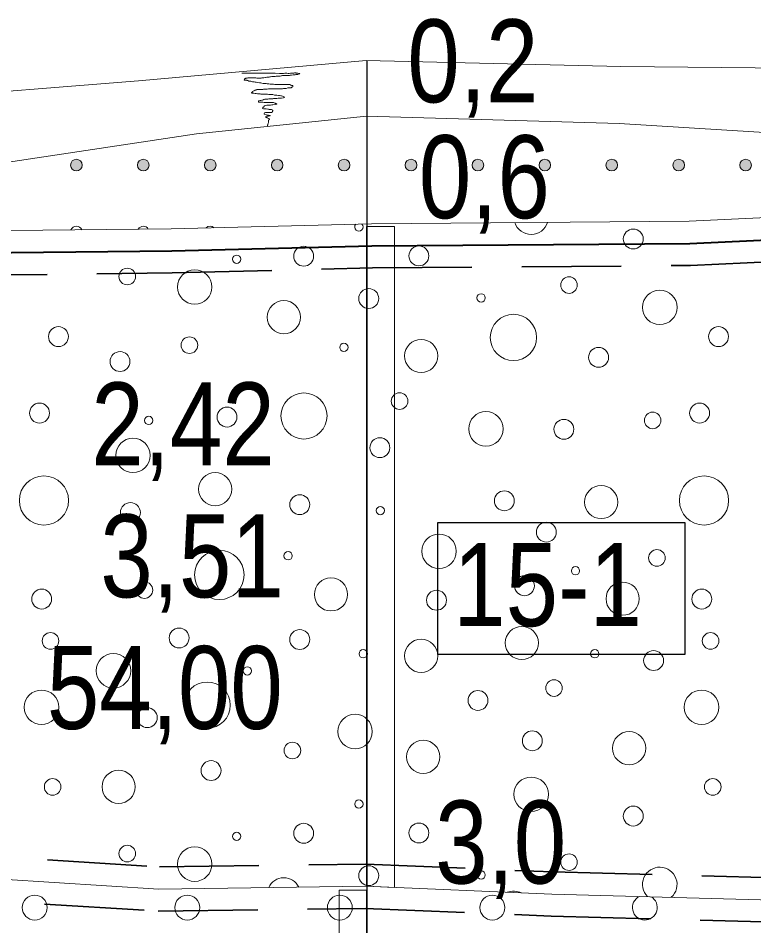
# Model space of a CAD drawing. Extents: x 640121 to 640955, y 6441885 to 6442246.
# Drawn here: x 640421.76 to 640448.36, y 6442180.31 to 6442213.13 of the extents above; entities that cross this region are included whole.
import ezdxf
from ezdxf.enums import TextEntityAlignment as Align

# ---------------------------------------------------------------- set-up
doc = ezdxf.new("R2010")
doc.units = 0
doc.header["$LTSCALE"] = 1.2
doc.linetypes.add('MEDIUM_DASHED', pattern=[4.5, 3, -1.5])
for name, color, linetype, lineweight in [('31', 7, 'Continuous', 13), ('32', 7, 'Continuous', 13), ('33', 7, 'Continuous', 13), ('35', 7, 'Continuous', 35), ('40', 7, 'Continuous', 13), ('41', 7, 'Continuous', 13), ('42', 7, 'Continuous', 13), ('45', 7, 'Continuous', 13)]:
    doc.layers.add(name, color=color, linetype=linetype, lineweight=lineweight)

msp = doc.modelspace()

# ---------------------------------------------------------------- hatches: boundary and pattern name
at = {"layer": '45'}
for points in [[(640424.077, 6442207.821, 1), (640423.657, 6442207.821, 1)], [(640426.497, 6442207.821, 1), (640426.077, 6442207.821, 1)], [(640428.917, 6442207.821, 1), (640428.497, 6442207.821, 1)], [(640431.337, 6442207.821, 1), (640430.917, 6442207.821, 1)], [(640433.757, 6442207.821, 1), (640433.337, 6442207.821, 1)], [(640436.177, 6442207.821, 1), (640435.757, 6442207.821, 1)], [(640438.597, 6442207.821, 1), (640438.177, 6442207.821, 1)], [(640441.017, 6442207.821, 1), (640440.597, 6442207.821, 1)], [(640443.437, 6442207.821, 1), (640443.017, 6442207.821, 1)], [(640445.857, 6442207.821, 1), (640445.437, 6442207.821, 1)], [(640448.277, 6442207.821, 1), (640447.857, 6442207.821, 1)]]:
    msp.add_hatch(color=256, dxfattribs=at).paths.add_polyline_path(points)

# ---------------------------------------------------------------- linework, layer by layer
at = {"layer": '31'}
for points in [[(640362.7, 6442207.53), (640371.1, 6442207.66), (640378.91, 6442207.96), (640387.66, 6442208.39), (640395.09, 6442208.91), (640403.04, 6442209.13), (640410.1, 6442209.62), (640417.94, 6442210.22), (640426.11, 6442210.87), (640434.35, 6442211.6), (640443.55, 6442211.39), (640450.84, 6442211.31), (640460.31, 6442211.42), (640471.64, 6442211.39), (640480.39, 6442211.46), (640490.9, 6442211.02), (640496.37, 6442211.02), (640502.28, 6442211.46), (640506.95, 6442212.04), (640510.5, 6442212.56)], [(640362.55, 6442203.68), (640369.1, 6442203.88), (640381.31, 6442204.1), (640393.24, 6442204.9), (640403.15, 6442205.61), (640412.11, 6442206.42), (640420.43, 6442207.78), (640428.21, 6442208.95), (640434.36, 6442209.59), (640443.5, 6442209.32), (640451.09, 6442208.86), (640456.15, 6442208.6), (640464.23, 6442208.39), (640474.43, 6442207.96), (640479.86, 6442207.51), (640485.77, 6442207.28), (640492.16, 6442206.96), (640495.99, 6442206.92), (640502.28, 6442207.34), (640510.5, 6442208.25)], [(640393.24, 6442204.9), (640408.33, 6442204.95), (640419.16, 6442205.43), (640427.3, 6442205.52), (640434.54, 6442205.7), (640446.03, 6442205.79), (640457.52, 6442206.33), (640468.28, 6442206.96), (640474.79, 6442207.15), (640481.17, 6442207.46)], [(640361.87, 6442180.35), (640370.38, 6442181.71), (640378.83, 6442182.99), (640382.86, 6442183.28), (640390.58, 6442183.39), (640398.35, 6442183.34), (640407.42, 6442182.84), (640417.38, 6442182.24), (640426.85, 6442181.64), (640434.32, 6442181.74), (640441.06, 6442181.46), (640449.93, 6442181.22), (640459.93, 6442181.24), (640467.81, 6442181.49), (640476.37, 6442181.44), (640484.64, 6442181.24), (640496.4, 6442181.04), (640502.87, 6442181.04), (640510.5, 6442181.13)]]:
    msp.add_lwpolyline(points, dxfattribs=at)
at = {"layer": '32', "lineweight": 25}
msp.add_line((640434.37, 6442211.6), (640434.37, 6442111.6), dxfattribs=at)
at = {"layer": '33'}
for points in [[(640435.37, 6442181.7), (640435.37, 6442205.6), (640434.36, 6442205.6), (640434.36, 6442181.74), (640434.36, 6442181.74)], [(640433.37, 6442181.6), (640433.37, 6442146.6), (640434.36, 6442146.6), (640434.36, 6442181.6)]]:
    msp.add_lwpolyline(points, close=True, dxfattribs=at)
at = {"layer": '33', "lineweight": 25}
msp.add_lwpolyline([(640436.94, 6442194.9), (640445.87, 6442194.9), (640445.87, 6442190.12), (640436.94, 6442190.12)], close=True, dxfattribs=at)
at = {"layer": '35', "lineweight": 40}
msp.add_lwpolyline([(640393.27, 6442204.1), (640408.35, 6442204.15), (640419.19, 6442204.63), (640427.32, 6442204.72), (640434.55, 6442204.9), (640446.05, 6442204.99), (640457.56, 6442205.53), (640468.31, 6442206.17), (640474.82, 6442206.35), (640481.18, 6442206.66)], dxfattribs=at)
at = {"layer": '35', "linetype": 'MEDIUM_DASHED'}
for points in [[(640393.27, 6442203.3), (640408.37, 6442203.35), (640419.21, 6442203.83), (640427.33, 6442203.92), (640434.57, 6442204.1), (640446.07, 6442204.19), (640457.6, 6442204.73), (640468.35, 6442205.37), (640474.85, 6442205.55), (640481.22, 6442205.86)], [(640379.57, 6442183.85), (640382.82, 6442184.08), (640390.58, 6442184.19), (640398.38, 6442184.14), (640407.47, 6442183.64), (640417.43, 6442183.04), (640426.87, 6442182.44), (640434.33, 6442182.54), (640441.09, 6442182.26), (640449.94, 6442182.02), (640459.92, 6442182.04), (640467.8, 6442182.29), (640476.38, 6442182.24), (640484.66, 6442182.04), (640494.87, 6442181.87)], [(640377.97, 6442182.13), (640382.89, 6442182.48), (640390.58, 6442182.59), (640398.33, 6442182.54), (640407.37, 6442182.04), (640417.33, 6442181.44), (640426.83, 6442180.84), (640434.31, 6442180.94), (640441.03, 6442180.66), (640449.92, 6442180.42), (640459.94, 6442180.44), (640467.82, 6442180.69), (640476.36, 6442180.64), (640484.62, 6442180.44), (640494.87, 6442180.27)]]:
    msp.add_lwpolyline(points, dxfattribs=at)
at = {"layer": '40'}
for points in [[(640429.85, 6442211.15), (640429.88, 6442211.15), (640429.93, 6442211.15), (640429.98, 6442211.15), (640430, 6442211.15), (640430.05, 6442211.15), (640430.13, 6442211.15), (640430.29, 6442211.15), (640430.38, 6442211.15), (640430.4, 6442211.15), (640430.42, 6442211.15), (640430.45, 6442211.15), (640430.49, 6442211.15), (640430.55, 6442211.15), (640430.59, 6442211.15), (640430.62, 6442211.15), (640430.66, 6442211.15), (640430.7, 6442211.15), (640430.73, 6442211.15), (640430.78, 6442211.15), (640430.8, 6442211.15), (640430.84, 6442211.15), (640430.88, 6442211.15), (640431.05, 6442211.14), (640431.21, 6442211.13), (640431.26, 6442211.13), (640431.29, 6442211.13), (640431.3, 6442211.13), (640431.33, 6442211.13), (640431.36, 6442211.13), (640431.41, 6442211.14), (640431.44, 6442211.14), (640431.45, 6442211.14), (640431.47, 6442211.14), (640431.48, 6442211.14), (640431.52, 6442211.13), (640431.54, 6442211.13), (640431.56, 6442211.13), (640431.61, 6442211.14), (640431.64, 6442211.14), (640431.68, 6442211.15), (640431.69, 6442211.15), (640431.73, 6442211.15), (640431.75, 6442211.16), (640431.77, 6442211.16), (640431.8, 6442211.16), (640431.81, 6442211.15), (640431.83, 6442211.15), (640431.86, 6442211.14), (640431.87, 6442211.14)], [(640430.61, 6442210.98), (640430.6, 6442210.98), (640430.57, 6442210.98), (640430.55, 6442210.97), (640430.53, 6442210.97), (640430.51, 6442210.97), (640430.49, 6442210.97), (640430.46, 6442210.97), (640430.44, 6442210.97), (640430.4, 6442210.97), (640430.39, 6442210.97), (640430.36, 6442210.98), (640430.34, 6442210.98), (640430.32, 6442210.98), (640430.3, 6442210.98), (640430.28, 6442210.98), (640430.25, 6442210.98), (640430.22, 6442210.98), (640430.2, 6442210.98), (640430.18, 6442210.98), (640430.15, 6442210.98), (640430.13, 6442210.98), (640430.11, 6442210.98), (640430.09, 6442210.98), (640430.07, 6442210.98), (640430.04, 6442210.97), (640430.03, 6442210.96), (640430, 6442210.96), (640429.98, 6442210.95), (640429.97, 6442210.95), (640429.96, 6442210.94), (640429.95, 6442210.93), (640429.94, 6442210.91), (640429.95, 6442210.89), (640430, 6442210.89), (640430.03, 6442210.89), (640430.04, 6442210.88), (640430.07, 6442210.88), (640430.09, 6442210.87), (640430.1, 6442210.86), (640430.13, 6442210.86), (640430.15, 6442210.86), (640430.17, 6442210.85), (640430.21, 6442210.84), (640430.24, 6442210.83), (640430.28, 6442210.83), (640430.3, 6442210.83), (640430.33, 6442210.82), (640430.37, 6442210.82), (640430.42, 6442210.81)], [(640431.87, 6442211.14), (640431.9, 6442211.13), (640431.92, 6442211.13), (640431.94, 6442211.13), (640431.95, 6442211.12), (640431.94, 6442211.12), (640431.95, 6442211.12), (640431.93, 6442211.12), (640431.9, 6442211.11), (640431.87, 6442211.1), (640431.86, 6442211.1), (640431.83, 6442211.1), (640431.81, 6442211.1), (640431.8, 6442211.1), (640431.78, 6442211.09), (640431.75, 6442211.09), (640431.72, 6442211.08), (640431.7, 6442211.08), (640431.64, 6442211.07), (640431.62, 6442211.07), (640431.6, 6442211.07), (640431.57, 6442211.06), (640431.55, 6442211.06), (640431.53, 6442211.06), (640431.5, 6442211.06), (640431.48, 6442211.06), (640431.43, 6442211.06), (640431.4, 6442211.06), (640431.36, 6442211.06), (640431.32, 6442211.06), (640431.29, 6442211.05), (640431.27, 6442211.05), (640431.24, 6442211.04), (640431.21, 6442211.04), (640431.12, 6442211.04), (640431.11, 6442211.04), (640431.09, 6442211.04), (640431.05, 6442211.03), (640431, 6442211.03), (640430.96, 6442211.02), (640430.93, 6442211.02), (640430.89, 6442211.01), (640430.86, 6442211.01), (640430.84, 6442211), (640430.81, 6442211), (640430.79, 6442211), (640430.78, 6442211), (640430.75, 6442211), (640430.72, 6442210.99), (640430.7, 6442210.99), (640430.64, 6442210.98), (640430.61, 6442210.98)], [(640430.42, 6442210.81), (640430.49, 6442210.8), (640430.54, 6442210.79), (640430.57, 6442210.78), (640430.62, 6442210.77), (640430.67, 6442210.77), (640430.7, 6442210.77), (640430.73, 6442210.77), (640430.76, 6442210.76), (640430.8, 6442210.76), (640430.83, 6442210.76), (640430.87, 6442210.75), (640430.91, 6442210.75), (640430.95, 6442210.75), (640431, 6442210.75), (640431.04, 6442210.74), (640431.07, 6442210.74), (640431.09, 6442210.74), (640431.12, 6442210.74), (640431.16, 6442210.74), (640431.2, 6442210.74), (640431.25, 6442210.74), (640431.29, 6442210.74), (640431.32, 6442210.74), (640431.36, 6442210.74), (640431.38, 6442210.74), (640431.41, 6442210.74), (640431.44, 6442210.74), (640431.47, 6442210.74), (640431.5, 6442210.74), (640431.53, 6442210.73), (640431.59, 6442210.73), (640431.62, 6442210.71), (640431.65, 6442210.7), (640431.68, 6442210.7), (640431.69, 6442210.69), (640431.69, 6442210.67), (640431.69, 6442210.65), (640431.68, 6442210.65), (640431.66, 6442210.64), (640431.65, 6442210.63), (640431.63, 6442210.62), (640431.59, 6442210.61), (640431.51, 6442210.61), (640431.45, 6442210.59), (640431.41, 6442210.59), (640431.36, 6442210.59), (640431.32, 6442210.58), (640431.27, 6442210.58), (640431.21, 6442210.58), (640431.11, 6442210.58), (640431.03, 6442210.58)], [(640431.03, 6442210.58), (640430.99, 6442210.58), (640430.95, 6442210.58), (640430.91, 6442210.58), (640430.88, 6442210.58), (640430.85, 6442210.58), (640430.81, 6442210.58), (640430.76, 6442210.57), (640430.67, 6442210.57), (640430.63, 6442210.57), (640430.61, 6442210.56), (640430.57, 6442210.56), (640430.51, 6442210.55), (640430.44, 6442210.55), (640430.42, 6442210.55), (640430.39, 6442210.55), (640430.37, 6442210.54), (640430.36, 6442210.53), (640430.34, 6442210.53), (640430.32, 6442210.53), (640430.3, 6442210.52), (640430.29, 6442210.51), (640430.26, 6442210.49), (640430.24, 6442210.48), (640430.24, 6442210.47), (640430.22, 6442210.46), (640430.21, 6442210.45), (640430.2, 6442210.44), (640430.19, 6442210.43), (640430.21, 6442210.42), (640430.22, 6442210.42), (640430.25, 6442210.42), (640430.28, 6442210.42), (640430.33, 6442210.41), (640430.37, 6442210.41), (640430.42, 6442210.4), (640430.48, 6442210.4), (640430.51, 6442210.4), (640430.54, 6442210.38), (640430.57, 6442210.38), (640430.66, 6442210.38), (640430.72, 6442210.38), (640430.78, 6442210.38), (640430.83, 6442210.37), (640430.9, 6442210.37), (640430.97, 6442210.37), (640431.03, 6442210.35), (640431.08, 6442210.35), (640431.12, 6442210.35), (640431.17, 6442210.34)], [(640431.17, 6442210.34), (640431.19, 6442210.34), (640431.21, 6442210.34), (640431.26, 6442210.32), (640431.29, 6442210.32), (640431.32, 6442210.31), (640431.34, 6442210.3), (640431.37, 6442210.29), (640431.38, 6442210.29), (640431.39, 6442210.26), (640431.38, 6442210.26), (640431.36, 6442210.25), (640431.35, 6442210.25), (640431.29, 6442210.24), (640431.26, 6442210.24), (640431.24, 6442210.24), (640431.2, 6442210.24), (640431.16, 6442210.24), (640431.12, 6442210.23), (640431.09, 6442210.23), (640431.07, 6442210.23), (640431, 6442210.23), (640430.97, 6442210.22), (640430.95, 6442210.22), (640430.92, 6442210.22), (640430.9, 6442210.22), (640430.87, 6442210.22), (640430.83, 6442210.22), (640430.79, 6442210.21), (640430.75, 6442210.2), (640430.72, 6442210.2), (640430.7, 6442210.2), (640430.68, 6442210.2), (640430.66, 6442210.19), (640430.63, 6442210.19), (640430.63, 6442210.18), (640430.6, 6442210.17), (640430.58, 6442210.17), (640430.57, 6442210.17), (640430.54, 6442210.16), (640430.51, 6442210.16), (640430.48, 6442210.15), (640430.46, 6442210.14), (640430.45, 6442210.13), (640430.45, 6442210.1), (640430.46, 6442210.1), (640430.5, 6442210.1), (640430.55, 6442210.1), (640430.59, 6442210.1), (640430.61, 6442210.1), (640430.66, 6442210.09), (640430.69, 6442210.09)], [(640430.69, 6442210.09), (640430.7, 6442210.08), (640430.72, 6442210.08), (640430.75, 6442210.08), (640430.79, 6442210.08), (640430.81, 6442210.08), (640430.86, 6442210.08), (640430.9, 6442210.08), (640430.92, 6442210.08), (640430.94, 6442210.08), (640430.96, 6442210.08), (640430.99, 6442210.08), (640431.02, 6442210.07), (640431.05, 6442210.06), (640431.07, 6442210.05), (640431.09, 6442210.05), (640431.11, 6442210.04), (640431.11, 6442210.02), (640431.05, 6442210.01), (640430.97, 6442210), (640430.94, 6442210), (640430.89, 6442209.99), (640430.86, 6442209.99), (640430.82, 6442209.99), (640430.79, 6442209.99), (640430.75, 6442209.99), (640430.72, 6442209.98), (640430.67, 6442209.96), (640430.66, 6442209.95), (640430.64, 6442209.93), (640430.63, 6442209.92), (640430.61, 6442209.91), (640430.61, 6442209.89), (640430.6, 6442209.87), (640430.61, 6442209.87), (640430.63, 6442209.86), (640430.67, 6442209.85), (640430.73, 6442209.85), (640430.79, 6442209.84), (640430.82, 6442209.84), (640430.84, 6442209.83), (640430.88, 6442209.83), (640430.92, 6442209.83), (640430.97, 6442209.81), (640430.97, 6442209.78), (640430.96, 6442209.77), (640430.96, 6442209.75), (640430.92, 6442209.72), (640430.9, 6442209.72), (640430.87, 6442209.72), (640430.83, 6442209.72), (640430.79, 6442209.72), (640430.75, 6442209.72), (640430.71, 6442209.72), (640430.67, 6442209.71), (640430.66, 6442209.69), (640430.66, 6442209.68), (640430.66, 6442209.66), (640430.68, 6442209.66), (640430.74, 6442209.64), (640430.78, 6442209.63), (640430.81, 6442209.63), (640430.84, 6442209.62), (640430.87, 6442209.62), (640430.88, 6442209.6), (640430.87, 6442209.6), (640430.84, 6442209.6), (640430.81, 6442209.59), (640430.76, 6442209.59), (640430.74, 6442209.59), (640430.72, 6442209.58), (640430.72, 6442209.56), (640430.73, 6442209.54), (640430.75, 6442209.54), (640430.76, 6442209.53), (640430.79, 6442209.52), (640430.82, 6442209.51), (640430.84, 6442209.51), (640430.85, 6442209.48), (640430.84, 6442209.47), (640430.83, 6442209.45), (640430.82, 6442209.44), (640430.81, 6442209.42), (640430.81, 6442209.4), (640430.81, 6442209.38), (640430.81, 6442209.36), (640430.8, 6442209.34), (640430.8, 6442209.32), (640430.79, 6442209.3), (640430.79, 6442209.28), (640430.78, 6442209.26), (640430.78, 6442209.24), (640430.78, 6442209.23), (640430.78, 6442209.25)]]:
    msp.add_lwpolyline(points, dxfattribs=at)
at = {"layer": '41'}
for centre, radius in [((640444.004, 6442205.149), 0.36), ((640432.086, 6442204.527), 0.36), ((640436.253, 6442204.537), 0.36), ((640429.663, 6442204.416), 0.15), ((640425.706, 6442203.792), 0.3), ((640428.145, 6442203.412), 0.624), ((640441.681, 6442203.483), 0.3), ((640434.439, 6442202.995), 0.36), ((640438.501, 6442203.018), 0.15), ((640444.963, 6442202.676), 0.624), ((640431.37, 6442202.319), 0.6), ((640439.671, 6442201.59), 0.838), ((640423.218, 6442201.619), 0.36), ((640447.087, 6442201.619), 0.36), ((640427.953, 6442201.308), 0.3), ((640436.332, 6442200.918), 0.6), ((640425.445, 6442200.716), 0.36), ((640433.539, 6442201.23), 0.15), ((640442.75, 6442200.868), 0.36), ((640432.097, 6442198.749), 0.834), ((640435.555, 6442199.286), 0.3), ((640422.534, 6442198.853), 0.36), ((640446.403, 6442198.853), 0.36), ((640429.314, 6442198.709), 0.36), ((640438.677, 6442198.281), 0.624), ((640444.705, 6442198.587), 0.3), ((640426.483, 6442198.587), 0.15), ((640441.496, 6442198.266), 0.36), ((640425.914, 6442197.323), 0.624), ((640434.842, 6442197.601), 0.36), ((640422.694, 6442195.691), 0.889), ((640428.886, 6442196.103), 0.6), ((640446.563, 6442195.691), 0.889), ((640442.845, 6442195.635), 0.6), ((640431.944, 6442195.542), 0.36), ((640439.343, 6442195.68), 0.36), ((640425.82, 6442195.256), 0.36), ((640434.859, 6442195.326), 0.15), ((640440.862, 6442194.548), 0.36), ((640436.981, 6442193.855), 0.624), ((640429.037, 6442193.002), 0.893), ((640431.523, 6442193.694), 0.15), ((640444.861, 6442193.616), 0.3), ((640441.915, 6442193.151), 0.15), ((640433.074, 6442192.296), 0.6), ((640440.07, 6442192.61), 0.36), ((640426.327, 6442192.452), 0.3), ((640443.619, 6442192.14), 0.6), ((640422.612, 6442192.127), 0.36), ((640436.889, 6442192.085), 0.36), ((640446.481, 6442192.127), 0.36), ((640422.93, 6442190.615), 0.3), ((640427.582, 6442190.72), 0.36), ((640431.944, 6442190.664), 0.36), ((640439.974, 6442190.54), 0.6), ((640446.799, 6442190.615), 0.3), ((640436.332, 6442190.072), 0.6), ((640434.238, 6442190.15), 0.15), ((640442.611, 6442190.15), 0.15), ((640444.74, 6442189.903), 0.36), ((640425.207, 6442189.534), 0.624), ((640430.05, 6442189.529), 0.15), ((640428.598, 6442188.292), 0.835), ((640441.138, 6442188.908), 0.3), ((640422.605, 6442188.214), 0.624), ((640438.389, 6442188.462), 0.36), ((640446.474, 6442188.214), 0.624), ((640426.43, 6442187.839), 0.36), ((640433.944, 6442187.336), 0.624), ((640440.353, 6442187.001), 0.36), ((640443.853, 6442186.733), 0.6), ((640431.679, 6442186.652), 0.3), ((640436.41, 6442186.421), 0.6), ((640428.737, 6442185.925), 0.36), ((640425.394, 6442185.338), 0.6), ((640440.312, 6442185.068), 0.624), ((640423.008, 6442185.335), 0.3), ((640446.877, 6442185.335), 0.3), ((640434.082, 6442184.714), 0.15), ((640444.004, 6442184.28), 0.36), ((640432.086, 6442183.658), 0.36), ((640436.253, 6442183.668), 0.36), ((640429.663, 6442183.547), 0.15), ((640425.706, 6442182.923), 0.3), ((640428.145, 6442182.543), 0.624), ((640441.681, 6442182.614), 0.3), ((640434.439, 6442182.126), 0.36), ((640438.501, 6442182.149), 0.15)]:
    msp.add_circle(centre, radius, dxfattribs=at)
for centre, radius, start, end in [((640434.082, 6442205.583), 0.15, 137.7468, 45.1174), ((640440.312, 6442205.937), 0.624, 198.5046, 342.3977), ((640444.963, 6442181.807), 0.624, 311.9186, 224.9816), ((640431.37, 6442181.45), 0.6, 25.5972, 155.9306), ((640439.671, 6442180.721), 0.838, 69.4762, 105.7349)]:
    msp.add_arc(centre, radius, start, end, dxfattribs=at)
at = {"layer": '42'}
for centre in [(640422.362, 6442180.971), (640427.878, 6442180.971), (640433.393, 6442180.971), (640438.909, 6442180.971)]:
    msp.add_circle(centre, 0.45, dxfattribs=at)
msp.add_arc((640444.424, 6442180.971), 0.45, 116.1928, 60.7074, dxfattribs=at)
at = {"layer": '45'}
for centre in [(640423.867, 6442207.821), (640426.287, 6442207.821), (640428.707, 6442207.821), (640431.127, 6442207.821), (640433.547, 6442207.821), (640435.967, 6442207.821), (640438.387, 6442207.821), (640440.807, 6442207.821), (640443.227, 6442207.821), (640445.647, 6442207.821), (640448.067, 6442207.821)]:
    msp.add_circle(centre, 0.21, dxfattribs=at)
for centre, start, end in [((640423.867, 6442205.401), 22.4905, 158.7826), ((640426.287, 6442205.401), 30.6549, 150.6183), ((640428.707, 6442205.401), 47.5608, 135.3034)]:
    msp.add_arc(centre, 0.21, start, end, dxfattribs=at)

# ---------------------------------------------------------------- texts
at = {"layer": '32', "width": 0.85}
for s, p in [('0,2', (640438.205, 6442210.09)), ('0,6', (640438.62, 6442205.9)), ('2,42', (640427.725, 6442196.96)), ('54,00', (640427.065, 6442187.43)), ('3,0', (640439.21, 6442181.84))]:
    msp.add_text(s, height=3, dxfattribs=at).set_placement(p, align=Align.CENTER)
at = {"layer": '33', "width": 0.85}
for s, p in [('3,51', (640428.05, 6442192.19)), ('15-1', (640440.905, 6442191.15))]:
    msp.add_text(s, height=3, dxfattribs=at).set_placement(p, align=Align.CENTER)

doc.saveas('drawing.dxf')
